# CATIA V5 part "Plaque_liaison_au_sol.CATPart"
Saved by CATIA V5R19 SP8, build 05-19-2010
Part number: Plaque_liaison_au_sol
Bounding box of the stored display mesh (mm): x -100 to 100, y -100 to 100, z 0 to 10
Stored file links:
  G:\EU_thinkMotion\CFAO_2010\MMS_groupe2\MMS_groupe2\OK\nrosalie\nrosalie_cfao_support_d_arme_legere_final\Plaque_liaison_au_sol.CATPart
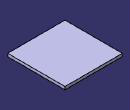
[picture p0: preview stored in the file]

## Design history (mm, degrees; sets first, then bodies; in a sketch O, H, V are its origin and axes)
Set1
  Sketch1 on xy-plane, origin (0, 0, 0), H (1, 0, 0), V (0, 1, 0)
    line L1 (-100, 100) -> (100, 100)
    line L2 (100, 100) -> (100, -100)
    line L3 (100, -100) -> (-100, -100)
    line L4 (-100, -100) -> (-100, 100)
    reference intersected line E1 through (0, 0) direction (0, 1) from yz-plane
    reference intersected line E2 through (0, 0) direction (-1, 0) from zx-plane
    length L1 = 200
    length L2 = 200
    horizontal: L1 H, L3 H
    vertical: L2 V, L4 V
    symmetry: L2 L4 E1, L3 L1 E2
Body1 (main body)
  Pad1: profile Sketch1, direction (0, 0, 1), length 10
